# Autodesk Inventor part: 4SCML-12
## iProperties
Created: 2011-01
Part Number: 4SCML-12
Document SubType Name: Modeling
Designer: ramunas
Author: ramunas
Translation Standard: STEP AP203
File Name: 4SCML-12.STEP
Preprocessor: SolidWorks 2003240
Postprocessor: Build: 272, Release: 10 SP3a - Date: Thu 12/15/2005
Sent Units: MILLIMETERS
Uncertainty: 1e-05
